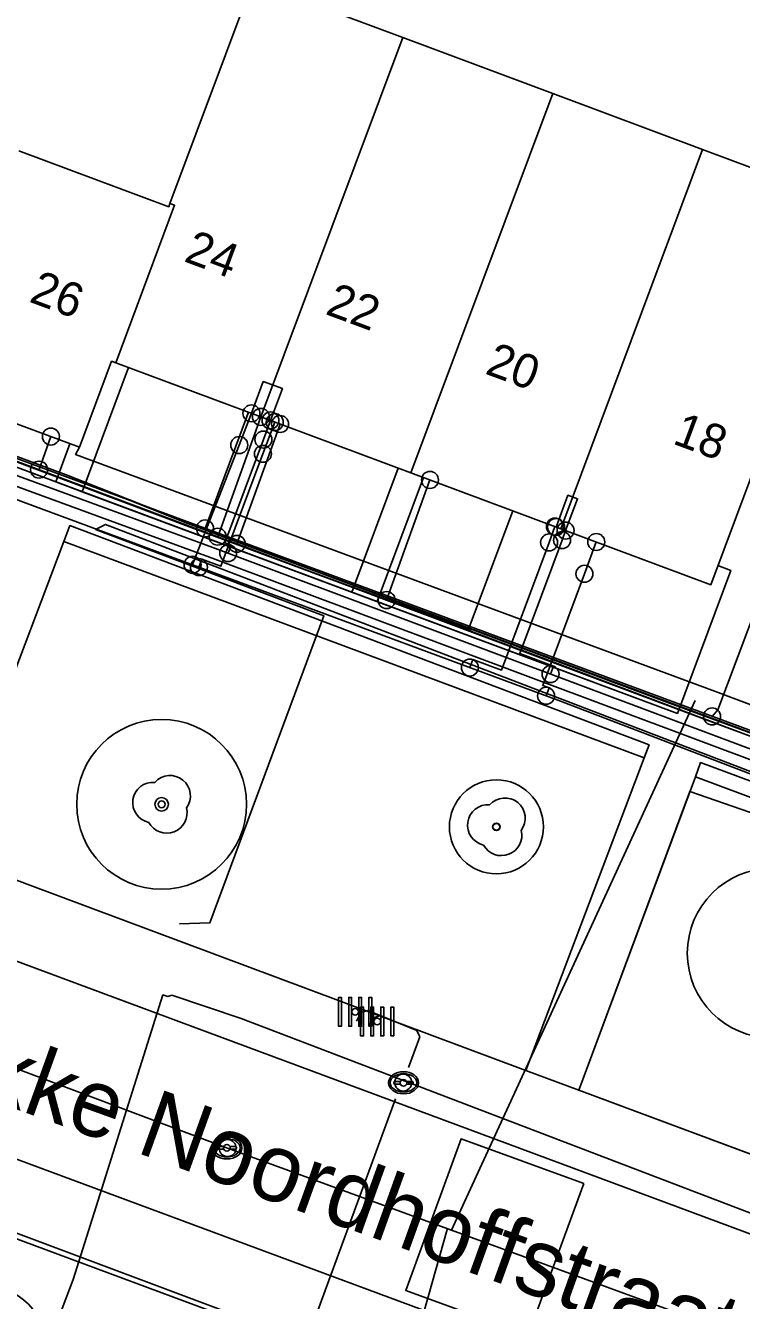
# Model space of a CAD drawing. Extents: x 192672 to 192910, y 446344 to 446512.
# Drawn here: x 192768.88 to 192789.96, y 446380.14 to 446417.71 of the extents above; entities that cross this region are included whole.
import ezdxf

# ---------------------------------------------------------------- set-up
doc = ezdxf.new("R2010")
doc.units = 0
for name, color, linetype in [('( Toegevoegd 29-11-2021 14_41_42) wegdeel vlak', 7, 'Continuous'), ('B-GV-GR-BOOM-S', 7, 'Continuous'), ('B-GV-KG-GRENS_WERKGRENS-G', 7, 'Continuous'), ('B-OI-KL-()_MANTELBUIS_WATER-G', 7, 'Continuous'), ('B-OI-KL-()_OVERIG_RIOOLVRIJVERVAL-S', 7, 'Continuous'), ('B-OI-KL-()_PUNTVANLEVERING_WATER-S', 7, 'Continuous'), ('B-OI-KL-BUISLEIDING_OLIEGASCHEMICALIEN_GASLAGEDRUK-G', 7, 'Continuous'), ('B-OI-KL-DATA-G', 7, 'Continuous'), ('B-OI-KL-DATA_GTWP-S', 7, 'Continuous'), ('B-OI-KL-DATA_KABELBED-G', 7, 'Continuous'), ('B-OI-KL-DATA_MOF-S', 7, 'Continuous'), ('B-OI-KL-ET_LS-G', 7, 'Continuous'), ('B-OI-KL-ET_LS_DELIVERYPOINT-S', 7, 'Continuous'), ('B-OI-KL-ET_LS_MOF-S', 7, 'Continuous'), ('B-OI-KL-ET_MS-G', 7, 'Continuous'), ('B-OI-KL-GAS_LD_AFTAKZADEL-S', 7, 'Continuous'), ('B-OI-KL-GAS_LD_DELIVERYPOINT-S', 7, 'Continuous'), ('B-OI-KL-GAS_LD_OVERGANGSSTUK-S', 7, 'Continuous'), ('B-OI-KL-WATER-G', 7, 'Continuous'), ('B-OI-RI-RIOOLVRIJVERVAL-G', 7, 'Continuous'), ('boom', 7, 'Continuous'), ('Default', 7, 'Continuous'), ('huisnummerreeks BGT', 7, 'Continuous'), ('inspectie-   rioolput', 7, 'Continuous'), ('kant open verharding', 7, 'Continuous'), ('kant verharding', 7, 'Continuous'), ('kolk', 7, 'Continuous'), ('pand op maaiveld vlak', 7, 'Continuous'), ('straatnaam', 7, 'Continuous'), ('verkeerseiland - berm', 7, 'Continuous')]:
    doc.layers.add(name, color=color, linetype=linetype)

# ---------------------------------------------------------------- blocks, each defined once
blk = doc.blocks.new('B-OI-KL-GAS_LD_AFTAKZADEL-S')
at = {"layer": 'Default'}
blk.add_circle((0, 0), 0.25, dxfattribs=at)
blk = doc.blocks.new('B-OI-KL-GAS_LD_DELIVERYPOINT-S')
at = {"layer": 'Default'}
blk.add_circle((0, 0), 0.25, dxfattribs=at)
blk = doc.blocks.new('B-OI-KL-GAS_LD_OVERGANGSSTUK-S')
at = {"layer": 'Default'}
blk.add_circle((0, 0), 0.25, dxfattribs=at)
blk = doc.blocks.new('B-OI-KL-ET_LS_DELIVERYPOINT-S')
at = {"layer": 'Default'}
blk.add_circle((0, 0), 0.25, dxfattribs=at)
blk = doc.blocks.new('B-OI-KL-ET_LS_MOF-S')
at = {"layer": 'Default'}
blk.add_circle((0, 0), 0.25, dxfattribs=at)
blk = doc.blocks.new('B-OI-KL-()_OVERIG_RIOOLVRIJVERVAL-S')
at = {"layer": 'Default'}
blk.add_circle((0, 0), 0.25, dxfattribs=at)
blk = doc.blocks.new('B-OI-KL-()_PUNTVANLEVERING_WATER-S')
at = {"layer": 'Default'}
blk.add_circle((0, 0), 0.25, dxfattribs=at)
blk = doc.blocks.new('B-OI-KL-DATA_GTWP-S')
at = {"layer": 'Default'}
blk.add_circle((0, 0), 0.25, dxfattribs=at)
blk = doc.blocks.new('B-OI-KL-DATA_MOF-S')
at = {"layer": 'Default'}
blk.add_circle((0, 0), 0.25, dxfattribs=at)

msp = doc.modelspace()

# ---------------------------------------------------------------- linework, layer by layer
at = {"layer": '( Toegevoegd 29-11-2021 14_41_42) wegdeel vlak'}
for points in [[(192807.071, 446391.618), (192806.989, 446391.38), (192789.199, 446398.084), (192788.212, 446398.449), (192770.35, 446405.075), (192770.467, 446405.283)], [(192787.1, 446396.135), (192787.242, 446396.51), (192770.185, 446402.974), (192770.009, 446402.51)], [(192806.008, 446389.049), (192806.18, 446389.51), (192788.76, 446395.99), (192788.604, 446395.572)]]:
    msp.add_lwpolyline(points, dxfattribs=at)
at = {"layer": 'B-GV-GR-BOOM-S'}
for centre, radius in [((192772.885, 446394.761), 2.5), ((192782.744, 446394.098), 1.384), ((192772.885, 446394.761), 0.2), ((192782.744, 446394.098), 0.111), ((192790.866, 446390.376), 2.5), ((192767.508, 446378.575), 2.054)]:
    msp.add_circle(centre, radius, dxfattribs=at)
at = {"layer": 'B-GV-KG-GRENS_WERKGRENS-G'}
msp.add_lwpolyline([(192788.443, 446395.14), (192806.008, 446389.049), (192802.587, 446379.853), (192794.566, 446382.838), (192790.602, 446384.314), (192785.169, 446386.336)], close=True, dxfattribs=at)
at = {"layer": 'B-OI-KL-()_MANTELBUIS_WATER-G'}
msp.add_lwpolyline([(192775.338, 446406.035), (192775.442, 446406.317)], dxfattribs=at)
at = {"layer": 'B-OI-KL-BUISLEIDING_OLIEGASCHEMICALIEN_GASLAGEDRUK-G'}
for points in [[(192825.926, 446382.49), (192824.393, 446382.916), (192820.049, 446384.609), (192801.561, 446391.312), (192784.629, 446397.804), (192756.601, 446408.196), (192751.089, 446410.462)], [(192775.173, 446405.35), (192775.53, 446406.284)], [(192775.87, 446405.09), (192776.219, 446406.027)], [(192773.796, 446401.821), (192773.883, 446402.055), (192775.173, 446405.35)], [(192773.984, 446401.751), (192774.071, 446401.986), (192774.633, 446401.777), (192775.87, 446405.09)], [(192784.295, 446402.479), (192784.469, 446402.947)], [(192781.964, 446398.792), (192782.051, 446399.026), (192782.89, 446398.715), (192784.295, 446402.479)], [(192785.338, 446401.556), (192785.687, 446402.492)], [(192784.207, 446397.96), (192784.294, 446398.195), (192784.109, 446398.263), (192785.338, 446401.556)]]:
    msp.add_lwpolyline(points, dxfattribs=at)
at = {"layer": 'B-OI-KL-DATA-G'}
for points in [[(192675.743, 446430.36), (192720.2, 446413.771), (192739.906, 446406.53), (192752.421, 446411.058), (192770.152, 446404.44), (192773.577, 446403.064), (192825.629, 446383.71), (192826.856, 446388.539), (192834.171, 446407.983), (192839.017, 446421.742), (192838.042, 446426.7), (192842.865, 446440.095), (192846.683, 446450.008), (192848.26, 446453.903), (192848.365, 446454.374), (192848.254, 446454.945), (192844.011, 446462.681), (192860.643, 446470.952)], [(192824.206, 446384.09), (192811.77, 446388.666), (192800.57, 446392.879), (192794.37, 446395.227), (192792.126, 446396.049), (192784.25, 446399.016), (192782.007, 446399.854), (192781.923, 446399.917), (192775.819, 446402.157), (192773.839, 446402.894), (192767.092, 446405.423), (192758.368, 446408.679), (192755.847, 446409.612), (192751.673, 446411.261), (192752.017, 446412.131), (192752.705, 446413.957), (192752.917, 446414.565), (192753.019, 446415.296), (192753.444, 446415.13)], [(192789.27, 446401.796), (192789.647, 446401.655), (192788.074, 446397.442), (192766.817, 446405.364), (192759.575, 446408.388), (192752.702, 446410.953), (192753.017, 446411.796)], [(192789.27, 446401.796), (192789.647, 446401.655), (192788.074, 446397.442), (192766.817, 446405.364), (192759.575, 446408.388), (192752.702, 446410.953), (192753.017, 446411.796)], [(192751.673, 446411.261), (192755.847, 446409.612), (192758.368, 446408.679), (192767.092, 446405.423), (192773.839, 446402.894), (192775.819, 446402.157), (192782.007, 446399.854), (192784.25, 446399.016), (192792.126, 446396.049), (192794.37, 446395.227), (192800.57, 446392.879), (192811.77, 446388.666), (192824.206, 446384.09), (192824.805, 446383.834)], [(192789.27, 446401.796), (192789.647, 446401.655), (192788.074, 446397.442), (192766.817, 446405.364), (192760.986, 446407.799), (192761.321, 446408.697)], [(192789.27, 446401.796), (192789.647, 446401.655), (192788.074, 446397.442), (192766.817, 446405.364), (192761.54, 446407.568), (192761.883, 446408.487)], [(192789.27, 446401.796), (192789.647, 446401.655), (192788.074, 446397.442), (192770.544, 446403.975), (192771.91, 446407.635)], [(192773.839, 446402.894), (192767.092, 446405.423)], [(192789.27, 446401.796), (192789.647, 446401.655), (192788.074, 446397.442), (192769.767, 446404.265), (192770.186, 446405.388)], [(192789.27, 446401.796), (192789.647, 446401.655), (192788.074, 446397.442), (192778.487, 446401.015), (192779.852, 446404.67)], [(192789.27, 446401.796), (192789.647, 446401.655), (192788.074, 446397.442), (192779.238, 446400.735), (192780.602, 446404.39)], [(192782.007, 446399.854), (192781.913, 446399.889), (192783.232, 446403.409)], [(192775.819, 446402.157), (192773.839, 446402.894)], [(192782.007, 446399.854), (192775.819, 446402.157)], [(192784.25, 446399.016), (192782.007, 446399.854)], [(192792.126, 446396.049), (192784.25, 446399.016)]]:
    msp.add_lwpolyline(points, dxfattribs=at)
at = {"layer": 'B-OI-KL-DATA_KABELBED-G'}
for points in [[(192821.01, 446385.323), (192810.079, 446389.386), (192802.298, 446392.278), (192800.939, 446392.783), (192793.524, 446395.538), (192789.077, 446397.191), (192779.512, 446400.781), (192775.099, 446402.438), (192774.537, 446402.649), (192761.96, 446407.369), (192758.326, 446408.733), (192752.386, 446410.963), (192751.738, 446411.209)], [(192761.54, 446407.568), (192766.817, 446405.364), (192769.767, 446404.265)], [(192770.544, 446403.975), (192771.91, 446407.635)], [(192774.537, 446402.649), (192775.811, 446406.179)], [(192775.099, 446402.438), (192776.373, 446405.969)], [(192769.275, 446404.624), (192769.624, 446405.598)], [(192769.767, 446404.265), (192770.186, 446405.388)], [(192778.487, 446401.015), (192779.852, 446404.67)], [(192769.767, 446404.265), (192770.544, 446403.975)], [(192779.238, 446400.735), (192780.602, 446404.39)], [(192779.512, 446400.781), (192780.789, 446404.32)], [(192770.544, 446403.975), (192778.487, 446401.015)], [(192788.074, 446397.442), (192789.647, 446401.655), (192789.27, 446401.796)], [(192778.487, 446401.015), (192779.238, 446400.735)], [(192779.238, 446400.735), (192788.074, 446397.442)], [(192744.469, 446391.186), (192762.819, 446384.291), (192799.152, 446370.668), (192816.75, 446364.01), (192817.485, 446363.735), (192812.909, 446351.776), (192812.803, 446351.499)]]:
    msp.add_lwpolyline(points, dxfattribs=at)
at = {"layer": 'B-OI-KL-ET_LS-G'}
for points in [[(192751.683, 446410.693), (192751.864, 446410.643), (192755.959, 446409.097), (192774.392, 446402.333), (192793.329, 446395.227), (192810.936, 446388.57), (192825.501, 446383.221), (192828.633, 446391.683), (192830.747, 446397.998), (192835.074, 446409.537), (192839.277, 446421.313), (192839.311, 446421.965), (192838.716, 446427.358), (192842.595, 446438.42)], [(192737.952, 446406.43), (192740.605, 446405.846), (192746.455, 446403.697), (192748.549, 446402.864), (192751.41, 446410.493), (192755.854, 446408.816), (192774.3, 446402.047), (192793.219, 446394.948), (192807.287, 446389.624)], [(192776.092, 446406.074), (192776.442, 446407.011), (192775.88, 446407.221), (192775.53, 446406.284)], [(192775.882, 446405.512), (192776.092, 446406.074)], [(192774.845, 446402.163), (192774.933, 446402.397), (192774.745, 446402.467), (192775.882, 446405.512)], [(192784.783, 446402.83), (192785.133, 446403.767), (192784.853, 446403.871), (192784.503, 446402.934)], [(192797.878, 446392.388), (192797.742, 446392.847), (192771.236, 446403.009), (192770.939, 446402.861)], [(192770.939, 446402.861), (192777.665, 446400.314), (192774.302, 446391.264), (192773.412, 446391.24)], [(192784.341, 446398.6), (192784.428, 446398.834), (192783.432, 446399.208), (192784.679, 446402.548)], [(192784.679, 446402.548), (192784.783, 446402.83)], [(192773.186, 446389.136), (192775.224, 446388.446), (192793.882, 446381.312), (192797.766, 446392.296), (192797.878, 446392.388)], [(192773.186, 446389.136), (192773.068, 446389.1), (192772.926, 446389.144), (192770.278, 446380.756), (192766.438, 446370.656), (192759.102, 446373.366), (192758.958, 446373.34)]]:
    msp.add_lwpolyline(points, dxfattribs=at)
at = {"layer": 'B-OI-KL-ET_MS-G'}
msp.add_lwpolyline([(192675.743, 446430.392), (192719.08, 446414.198), (192720.2, 446413.771), (192739.907, 446406.53), (192740.419, 446406.767), (192749.859, 446410.199), (192752.421, 446411.058), (192770.152, 446404.44), (192774.571, 446402.692), (192787.766, 446397.768), (192806.764, 446390.772), (192825.096, 446383.91)], dxfattribs=at)
at = {"layer": 'B-OI-KL-WATER-G'}
for points in [[(192742.681, 446414.565), (192743.85, 446414.136), (192825.105, 446383.994)], [(192774.164, 446402.891), (192775.442, 446406.317)], [(192789.096, 446397.352), (192789.267, 446397.55), (192790.468, 446400.729)]]:
    msp.add_lwpolyline(points, dxfattribs=at)
at = {"layer": 'B-OI-RI-RIOOLVRIJVERVAL-G'}
for points in [[(192781.411, 446382.19), (192788.603, 446397.817)], [(192757.91, 446391), (192774.83, 446384.63)], [(192780.4, 446388.097), (192778.954, 446388.688), (192778.757, 446388.628), (192778.621, 446388.371)], [(192779.123, 446388.467), (192778.996, 446388.232)], [(192779.328, 446388.535), (192779.123, 446388.467)], [(192780.494, 446387.911), (192780.16, 446387.001)], [(192780.4, 446388.097), (192780.494, 446387.911)], [(192776.875, 446378.183), (192779.771, 446386.078)], [(192774.83, 446384.63), (192791.8, 446378.41)], [(192781.29, 446382.235), (192776.629, 446365.694)]]:
    msp.add_lwpolyline(points, dxfattribs=at)
at = {"layer": 'boom'}
for centre in [(192772.885, 446394.761), (192782.744, 446394.098)]:
    msp.add_circle(centre, 0.1, dxfattribs=at)
for centre, radius, start, end in [((192772.635, 446394.811), 0.6, 85.137, 257.7544), ((192773.135, 446395.011), 0.6, 323.5446, 138.4658), ((192773.035, 446394.511), 0.6, 208.5058, 13.8356), ((192772.885, 446394.761), 0.1, 0, 180), ((192772.885, 446394.761), 0.1, 180, 0), ((192782.494, 446394.148), 0.6, 85.137, 257.7544), ((192782.994, 446394.348), 0.6, 323.5446, 138.4658), ((192782.894, 446393.848), 0.6, 208.5058, 13.8356), ((192782.744, 446394.098), 0.1, 0, 180), ((192782.744, 446394.098), 0.1, 180, 0)]:
    msp.add_arc(centre, radius, start, end, dxfattribs=at)
at = {"layer": 'inspectie-   rioolput'}
for p, q in [((192779.917, 446386.591), (192779.76, 446386.591)), ((192779.76, 446386.517), (192779.917, 446386.517)), ((192780.26, 446386.591), (192780.103, 446386.591)), ((192780.103, 446386.517), (192780.26, 446386.517)), ((192774.715, 446384.675), (192774.558, 446384.675)), ((192774.558, 446384.6), (192774.715, 446384.6)), ((192775.058, 446384.675), (192774.901, 446384.675)), ((192774.901, 446384.6), (192775.058, 446384.6))]:
    msp.add_line(p, q, dxfattribs=at)
for centre, radius, start, end in [((192779.76, 446386.554), 0.0375, 90, 270), ((192780.01, 446386.554), 0.1, 0, 180), ((192780.01, 446386.554), 0.1, 157.9757, 180), ((192780.01, 446386.554), 0.1, 180, 202.0243), ((192780.01, 446386.554), 0.1, 180, 0), ((192780.01, 446386.554), 0.1, 0, 22.0243), ((192780.01, 446386.554), 0.1, 337.9757, 0), ((192780.26, 446386.554), 0.0375, 270, 90), ((192774.558, 446384.637), 0.0375, 90, 270), ((192774.808, 446384.637), 0.1, 0, 180), ((192774.808, 446384.637), 0.1, 157.9757, 180), ((192774.808, 446384.637), 0.1, 180, 202.0243), ((192774.808, 446384.637), 0.1, 180, 0), ((192774.808, 446384.637), 0.1, 0, 22.0243), ((192774.808, 446384.637), 0.1, 337.9757, 0), ((192775.058, 446384.637), 0.0375, 270, 90)]:
    msp.add_arc(centre, radius, start, end, dxfattribs=at)
for centre, major_axis, ratio in [((192780.01, 446386.554), (-0.442, 0), 0.73911), ((192780.01, 446386.554), (-0.392, 0), 0.689655), ((192774.808, 446384.637), (-0.442, 0), 0.73911), ((192774.808, 446384.637), (-0.392, 0), 0.689655)]:
    msp.add_ellipse(centre, major_axis=major_axis, ratio=ratio, dxfattribs=at)
at = {"layer": 'kant open verharding'}
msp.add_lwpolyline([(192785.316, 446383.588), (192781.705, 446384.906), (192780.074, 446380.436), (192783.685, 446379.118), (192785.316, 446383.588)], dxfattribs=at)
at = {"layer": 'kant verharding'}
for p, q in [((192753.133, 446395.89), (192813.567, 446373.412)), ((192751.186, 446390.775), (192811.557, 446368.364)), ((192785.169, 446386.336), (192783.608, 446386.92))]:
    msp.add_line(p, q, dxfattribs=at)
at = {"layer": 'kolk'}
for points in [[(192778.181, 446388.645), (192778.181, 446389.07), (192778.096, 446389.07), (192778.096, 446388.645), (192778.096, 446388.22), (192778.181, 446388.22)], [(192778.479, 446388.645), (192778.479, 446389.07), (192778.394, 446389.07), (192778.394, 446388.645), (192778.394, 446388.22), (192778.479, 446388.22)], [(192778.776, 446388.645), (192778.776, 446389.07), (192778.691, 446389.07), (192778.691, 446388.645), (192778.691, 446388.22), (192778.776, 446388.22)], [(192779.074, 446388.645), (192779.074, 446389.07), (192778.989, 446389.07), (192778.989, 446388.645), (192778.989, 446388.22), (192779.074, 446388.22)], [(192778.831, 446388.36), (192778.831, 446388.785), (192778.746, 446388.785), (192778.746, 446388.36), (192778.746, 446387.935), (192778.831, 446387.935)], [(192779.129, 446388.36), (192779.129, 446388.785), (192779.044, 446388.785), (192779.044, 446388.36), (192779.044, 446387.935), (192779.129, 446387.935)], [(192779.426, 446388.36), (192779.426, 446388.785), (192779.341, 446388.785), (192779.341, 446388.36), (192779.341, 446387.935), (192779.426, 446387.935)], [(192779.724, 446388.36), (192779.724, 446388.785), (192779.639, 446388.785), (192779.639, 446388.36), (192779.639, 446387.935), (192779.724, 446387.935)]]:
    msp.add_lwpolyline(points, close=True, dxfattribs=at)
for centre, start, end in [((192778.585, 446388.645), 0, 180), ((192778.585, 446388.645), 180, 0), ((192779.235, 446388.36), 0, 180), ((192779.235, 446388.36), 180, 0)]:
    msp.add_arc(centre, 0.1, start, end, dxfattribs=at)
at = {"layer": 'pand op maaiveld vlak'}
for p, q in [((192779.986, 446417.36), (192775.811, 446406.179)), ((192784.402, 446415.712), (192779.986, 446417.36)), ((192780.227, 446404.53), (192784.402, 446415.712)), ((192784.402, 446415.712), (192788.818, 446414.063)), ((192784.643, 446402.882), (192788.818, 446414.063)), ((192775.811, 446406.179), (192771.535, 446407.775)), ((192766.034, 446406.937), (192770.467, 446405.283)), ((192780.227, 446404.53), (192775.811, 446406.179)), ((192780.227, 446404.53), (192784.643, 446402.882))]:
    msp.add_line(p, q, dxfattribs=at)
for points in [[(192779.986, 446417.36), (192775.57, 446419.009), (192773.128, 446412.468)], [(192773.128, 446412.468), (192773.093, 446412.373), (192768.678, 446414.021)], [(192784.643, 446402.882), (192789.06, 446401.234), (192791.717, 446408.352), (192793.234, 446412.413), (192788.818, 446414.063)], [(192771.535, 446407.775), (192773.267, 446412.416), (192773.128, 446412.468)], [(192771.535, 446407.775), (192771.414, 446407.82), (192770.467, 446405.283)]]:
    msp.add_lwpolyline(points, dxfattribs=at)
at = {"layer": 'verkeerseiland - berm'}
for p, q in [((192770.009, 446402.51), (192766.521, 446393.307)), ((192787.1, 446396.135), (192770.009, 446402.51)), ((192787.1, 446396.135), (192783.608, 446386.92)), ((192788.604, 446395.572), (192785.169, 446386.336)), ((192806.008, 446389.049), (192788.604, 446395.572)), ((192783.608, 446386.92), (192766.521, 446393.307)), ((192785.169, 446386.336), (192802.587, 446379.853)), ((192762.674, 446384.166), (192780.156, 446377.668))]:
    msp.add_line(p, q, dxfattribs=at)

# ---------------------------------------------------------------- block references
at = {"layer": 'B-OI-KL-()_OVERIG_RIOOLVRIJVERVAL-S'}
for p in [(192780, 446386.56), (192774.83, 446384.63)]:
    msp.add_blockref('B-OI-KL-()_OVERIG_RIOOLVRIJVERVAL-S', p, dxfattribs=at)
at = {"layer": 'B-OI-KL-()_PUNTVANLEVERING_WATER-S'}
for p in [(192774.164, 446402.891), (192789.096, 446397.352)]:
    msp.add_blockref('B-OI-KL-()_PUNTVANLEVERING_WATER-S', p, dxfattribs=at)
at = {"layer": 'B-OI-KL-DATA_GTWP-S'}
for p in [(192775.811, 446406.179), (192776.373, 446405.969), (192769.624, 446405.598), (192769.275, 446404.624), (192780.789, 446404.32), (192774.537, 446402.649), (192775.099, 446402.438), (192779.512, 446400.781)]:
    msp.add_blockref('B-OI-KL-DATA_GTWP-S', p, dxfattribs=at)
at = {"layer": 'B-OI-KL-DATA_MOF-S'}
for p in [(192769.275, 446404.624), (192774.537, 446402.649), (192775.099, 446402.438), (192779.512, 446400.781)]:
    msp.add_blockref('B-OI-KL-DATA_MOF-S', p, dxfattribs=at)
at = {"layer": 'B-OI-KL-ET_LS_DELIVERYPOINT-S'}
for p in [(192775.53, 446406.284), (192776.092, 446406.074), (192784.503, 446402.934), (192784.783, 446402.83)]:
    msp.add_blockref('B-OI-KL-ET_LS_DELIVERYPOINT-S', p, dxfattribs=at)
at = {"layer": 'B-OI-KL-ET_LS_MOF-S'}
for p in [(192775.882, 446405.512), (192784.679, 446402.548), (192774.845, 446402.163), (192784.341, 446398.6)]:
    msp.add_blockref('B-OI-KL-ET_LS_MOF-S', p, dxfattribs=at)
at = {"layer": 'B-OI-KL-GAS_LD_AFTAKZADEL-S'}
for p in [(192773.796, 446401.821), (192773.984, 446401.751), (192781.964, 446398.792), (192784.207, 446397.96)]:
    msp.add_blockref('B-OI-KL-GAS_LD_AFTAKZADEL-S', p, dxfattribs=at)
at = {"layer": 'B-OI-KL-GAS_LD_DELIVERYPOINT-S'}
for p in [(192775.53, 446406.284), (192776.219, 446406.027), (192784.469, 446402.947), (192785.687, 446402.492)]:
    msp.add_blockref('B-OI-KL-GAS_LD_DELIVERYPOINT-S', p, dxfattribs=at)
at = {"layer": 'B-OI-KL-GAS_LD_OVERGANGSSTUK-S'}
for p in [(192775.173, 446405.35), (192775.87, 446405.09), (192784.295, 446402.479), (192785.338, 446401.556)]:
    msp.add_blockref('B-OI-KL-GAS_LD_OVERGANGSSTUK-S', p, dxfattribs=at)

# ---------------------------------------------------------------- texts
at = {"layer": 'huisnummerreeks BGT'}
for s, p in [('24', (192773.511, 446410.773)), ('26', (192768.952, 446409.583)), ('22', (192777.675, 446409.219)), ('20', (192782.378, 446407.463)), ('18', (192787.901, 446405.402))]:
    msp.add_text(s, height=1, rotation=339.6, dxfattribs=at).set_placement(p)
at = {"layer": 'straatnaam'}
msp.add_text('Fokke Noordhoffstraat', height=2, rotation=340.2, dxfattribs=at).set_placement((192764.533, 446387.236))

doc.saveas('drawing.dxf')
